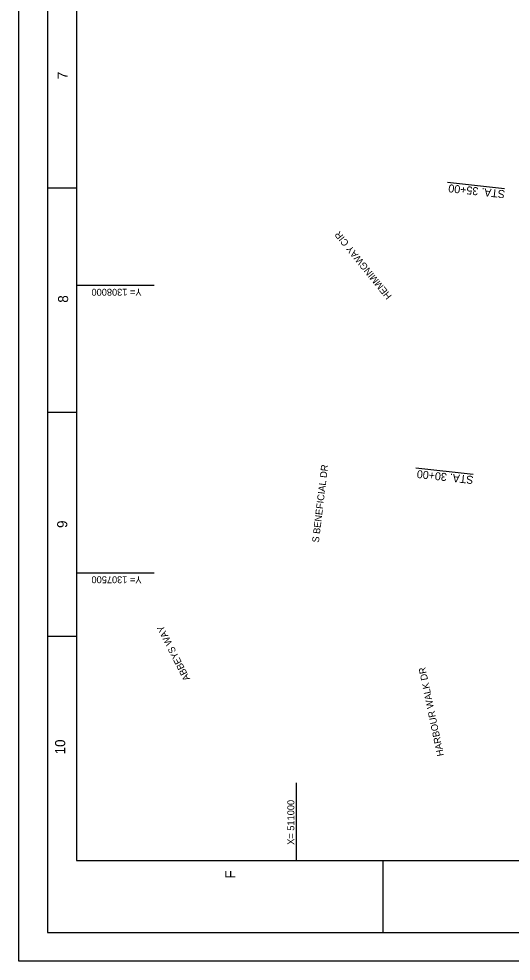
# Model space of a CAD drawing. Extents: x 510517 to 513917, y 1306825 to 1311225.
# Drawn here: x 510517 to 511373, y 1306825 to 1308464 of the extents above; entities that cross this region are included whole.
import ezdxf

# ---------------------------------------------------------------- set-up
doc = ezdxf.new("R2010")
doc.units = 0
for name, color, linetype in [('G-ANNO-NPLT', 7, 'Continuous'), ('G-ANNO-TTLB', 7, 'Continuous'), ('V-ALGN-TEXT', 7, 'Continuous'), ('V-ROAD-IDEN', 7, 'Continuous'), ('V-TOPO-COOR-STAT', 7, 'Continuous')]:
    doc.layers.add(name, color=color, linetype=linetype)

msp = doc.modelspace()

# ---------------------------------------------------------------- linework, layer by layer
at = {"layer": 'G-ANNO-NPLT'}
msp.add_lwpolyline([(510517.1, 1306825.1), (510517.1, 1311225.1), (513917.1, 1311225.1), (513917.1, 1306825.1)], close=True, dxfattribs=at)
msp.add_lwpolyline([(510567.1, 1306825.1), (510517.1, 1306825.1), (510517.1, 1306875.1)], dxfattribs=at)
at = {"layer": 'G-ANNO-TTLB'}
for p, q in [((510567.1, 1308170.1), (510617.1, 1308170.1)), ((510567.1, 1307780.1), (510617.1, 1307780.1)), ((510567.1, 1307780.1), (510617.1, 1307780.1)), ((510567.1, 1307390.1), (510617.1, 1307390.1)), ((511150.6, 1306875.1), (511150.6, 1307000.1))]:
    msp.add_line(p, q, dxfattribs=at)
for points in [[(513867.1, 1306875.1), (513867.1, 1311175.1), (510567.1, 1311175.1), (510567.1, 1306875.1)], [(510617.1, 1311125.1), (510617.1, 1307000.1), (513817.1, 1307000.1), (513817.1, 1311125.1)]]:
    msp.add_lwpolyline(points, close=True, dxfattribs=at)
at = {"layer": 'V-ALGN-TEXT'}
for p, q in [((511361.6, 1308168.6), (511262.2, 1308179.5)), ((511306.9, 1307671.6), (511207.5, 1307682.5))]:
    msp.add_line(p, q, dxfattribs=at)
at = {"layer": 'V-TOPO-COOR-STAT'}
for p, q in [((510752.1, 1308000), (510617.1, 1308000)), ((510752.1, 1307500), (510617.1, 1307500)), ((511000, 1307000.1), (511000, 1307135.1))]:
    msp.add_line(p, q, dxfattribs=at)

# ---------------------------------------------------------------- texts
at = {"layer": 'G-ANNO-TTLB'}
for s, p in [('7', (510602.1, 1308359)), ('8', (510602.8, 1307970.3)), ('9', (510601.2, 1307578.5)), ('10', (510597.7, 1307184.7)), ('F', (510893.5, 1306968.7))]:
    msp.add_text(s, height=17.5, rotation=90, dxfattribs=at).set_placement(p)
at = {"layer": 'V-ALGN-TEXT'}
for s, p in [('STA. 35+00', (511363, 1308165.6)), ('STA. 30+00', (511308.2, 1307668.6))]:
    msp.add_text(s, height=13.92, rotation=173.7132, dxfattribs=at).set_placement(p)
at = {"layer": 'V-ROAD-IDEN'}
for s, rotation, p in [('HEMMINGWAY CIR', 128.8905, (511166.2, 1307982.1)), ('S BENEFICIAL DR', 83.145, (511038.7, 1307552.6)), ('ABBEYS WAY', 116.8671, (510815.2, 1307316.3)), ('HARBOUR WALK DR', 101.8837, (511256.3, 1307182.9))]:
    msp.add_text(s, height=12, rotation=rotation, dxfattribs=at).set_placement(p)
at = {"layer": 'V-TOPO-COOR-STAT'}
for s, rotation, p in [('Y= 1308000', 180, (510730.4, 1307994.5)), ('Y= 1307500', 180, (510730.4, 1307494.5)), ('X= 511000', 90, (510996, 1307027.5))]:
    msp.add_text(s, height=12, rotation=rotation, dxfattribs=at).set_placement(p)

doc.saveas('drawing.dxf')
